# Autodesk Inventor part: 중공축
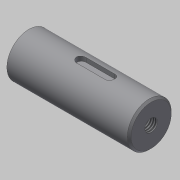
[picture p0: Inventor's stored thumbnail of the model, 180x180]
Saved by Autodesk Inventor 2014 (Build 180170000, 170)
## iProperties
Created: 2019-10
Part Number: 중공축
Material: 강철, 탄소
Document SubType Name: Modeling
Designer: mduedu
Density: 1 g/cm^3
Appearance: Default
Author: mduedu
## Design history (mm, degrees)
sketch "스케치1"
  geometry: L1 (0, 0)-(64, 0); L2 (64, 0)-(64, 11.5); L3 (64, 11.5)-(0, 11.5); L4 (0, 11.5)-(0, 0)
  constraints: 8 end point, 2 parallel, 1 horizontal, 1 perpendicular
  dimensions: "d0" = 64 distance of L2.end L3.end; "d2" = 23 diameter of L3 L1
revolve "회전1" sketch "스케치1" stored, may be unused: angle "d3" = 90 deg
hole "구멍1" diameter "d6" = 6.647; stored, may be unused: countersink angle "d10" = 90 deg, drill point angle "d12" = 118 deg; dims "d4" = 10, "d5" = 10, "d7" = 6, "d8" = 4, "d9" = 2, "d11" = 8
hole "구멍2" diameter "d15" = 13; stored, may be unused: countersink angle "d19" = 90 deg, drill point angle "d21" = 0 deg; dims "d13" = 10, "d14" = 10, "d16" = 6, "d17" = 15, "d18" = 20, "d20" = 32
sketch "스케치2"
  geometry: L1 (20, -7.5)-(20, -6.5) reference; L2 (20, -6.5)-(52, -6.5) reference; L3 (52, -6.5)-(52, -3.324) reference; L4 (52, -3.324)-(64, -3.324) reference; L5 (64, -3.324)-(64, -11.5) reference; L6 (64, -11.5)-(0, -11.5) reference; L7 (0, -11.5)-(0, -7.5) reference; L8 (0, -7.5)-(20, -7.5) reference; L9 (20, 6.5)-(20, 7.5) reference; L10 (20, 7.5)-(0, 7.5) reference; L11 (0, 7.5)-(0, 11.5) reference; L12 (0, 11.5)-(64, 11.5) reference; L13 (64, 11.5)-(64, 3.324) reference; L14 (64, 3.324)-(52, 3.324) reference; L15 (52, 3.324)-(52, 6.5) reference; L16 (52, 6.5)-(20, 6.5) reference; L17 (25, 11.5)-(45, 11.5); L18 (45, 11.5)-(45, 9); L19 (45, 9)-(25, 9); L20 (25, 9)-(25, 11.5); 1 further point
  constraints: 8 end point, 2 parallel, 1 horizontal, 1 perpendicular, 1 point on line
  dimensions: "d22" = 20 distance of L17.start L17.end; "d24" = 25 distance between parallel lines of L20 L11; "d25" = 2.5 distance of L17.end L18.end
extrude "돌출1" cut sketch "스케치2" stored distance "d26" = 5; taper "d27" = 0 deg
fillet "모깎기1"
fillet "모깎기2"
sketch "스케치3"
  geometry: 3 further points
  constraints: 2 vertical alignment, 1 other
hole "구멍3" sketch "스케치3" at (0, 7.5) diameter "d28" = 2.459; stored, may be unused: countersink angle "d32" = 90 deg, drill point angle "d34" = 118 deg; dims "d29" = 6, "d30" = 4, "d31" = 2, "d33" = 8
chamfer "모따기1" distance "d35" = 1; stored, may be unused: second distance "d36" = 2, angle "d37" = 45 deg
node "솔리드1"
node "절단 모서리 투영1"
